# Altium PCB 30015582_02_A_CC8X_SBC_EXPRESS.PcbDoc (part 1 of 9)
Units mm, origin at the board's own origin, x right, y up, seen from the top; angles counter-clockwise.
Board outline 87 x 63 mm, 6 copper layers (Top Layer-L1, GND Plane-L2, Signal-L3, PWR/Signal-L4, GND Plane-L5, Bottom Layer-L6), stack 1.172 mm thick; 169 components, 171 nets, 693 pads, 391 vias.
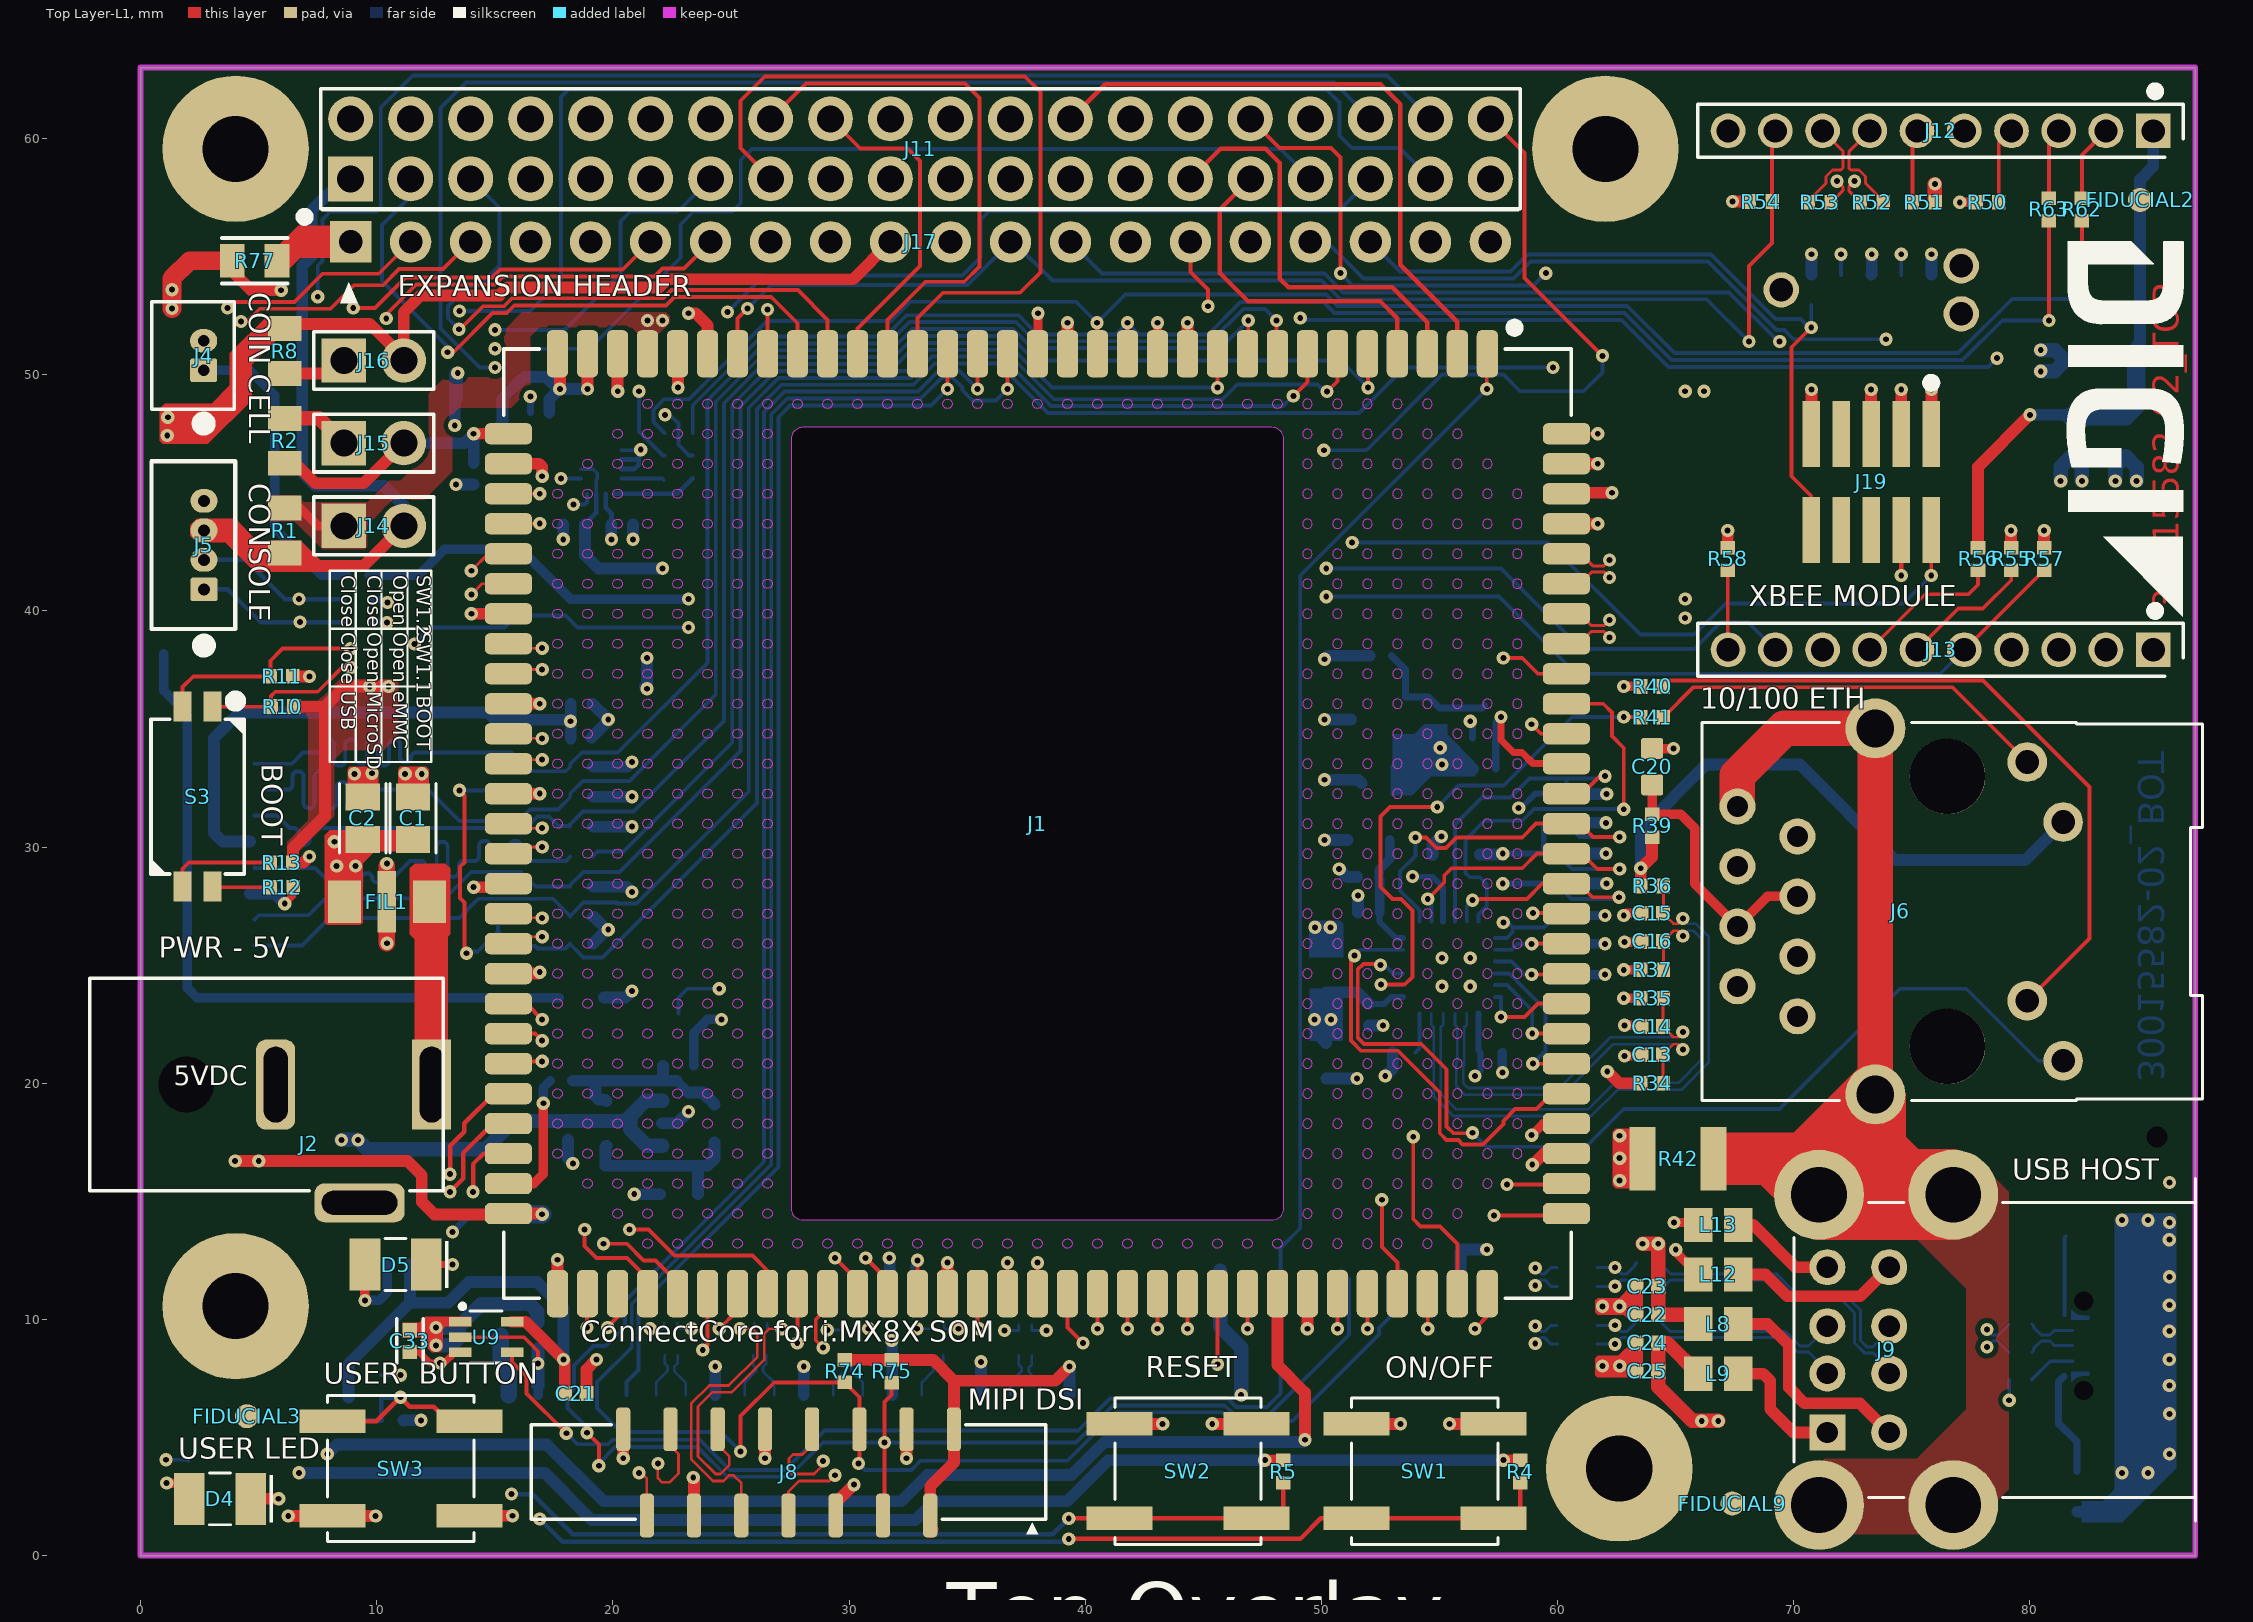
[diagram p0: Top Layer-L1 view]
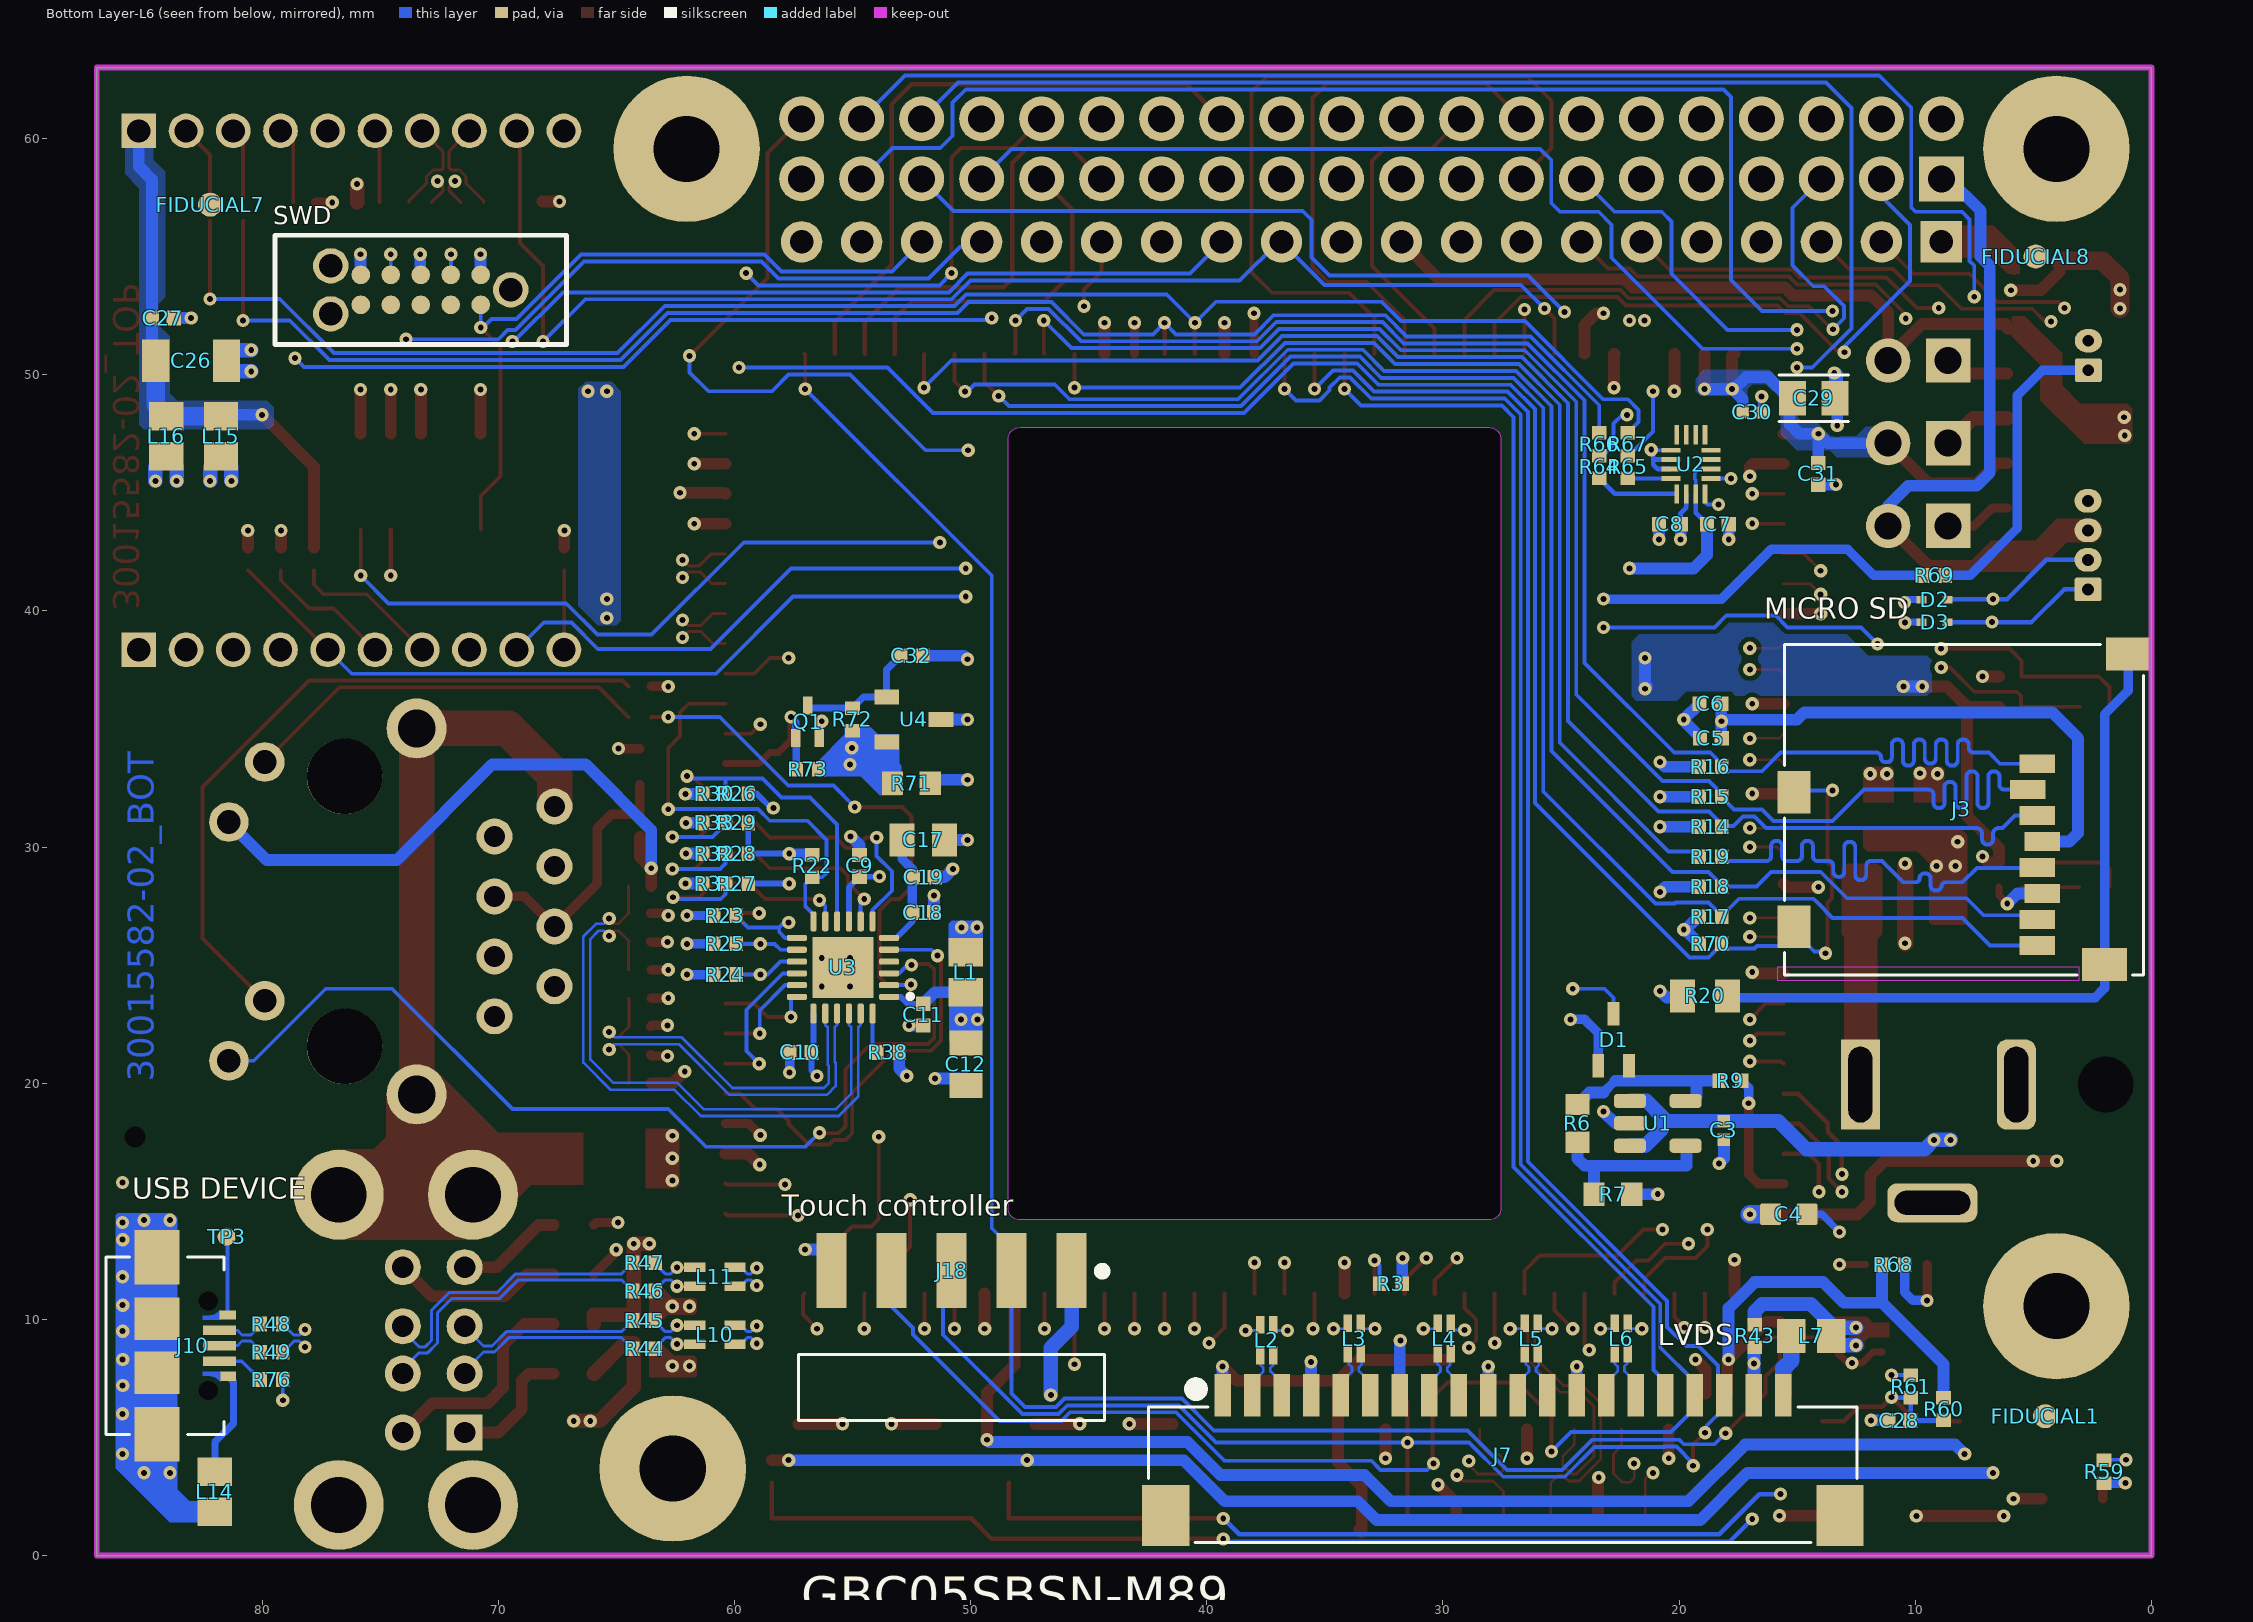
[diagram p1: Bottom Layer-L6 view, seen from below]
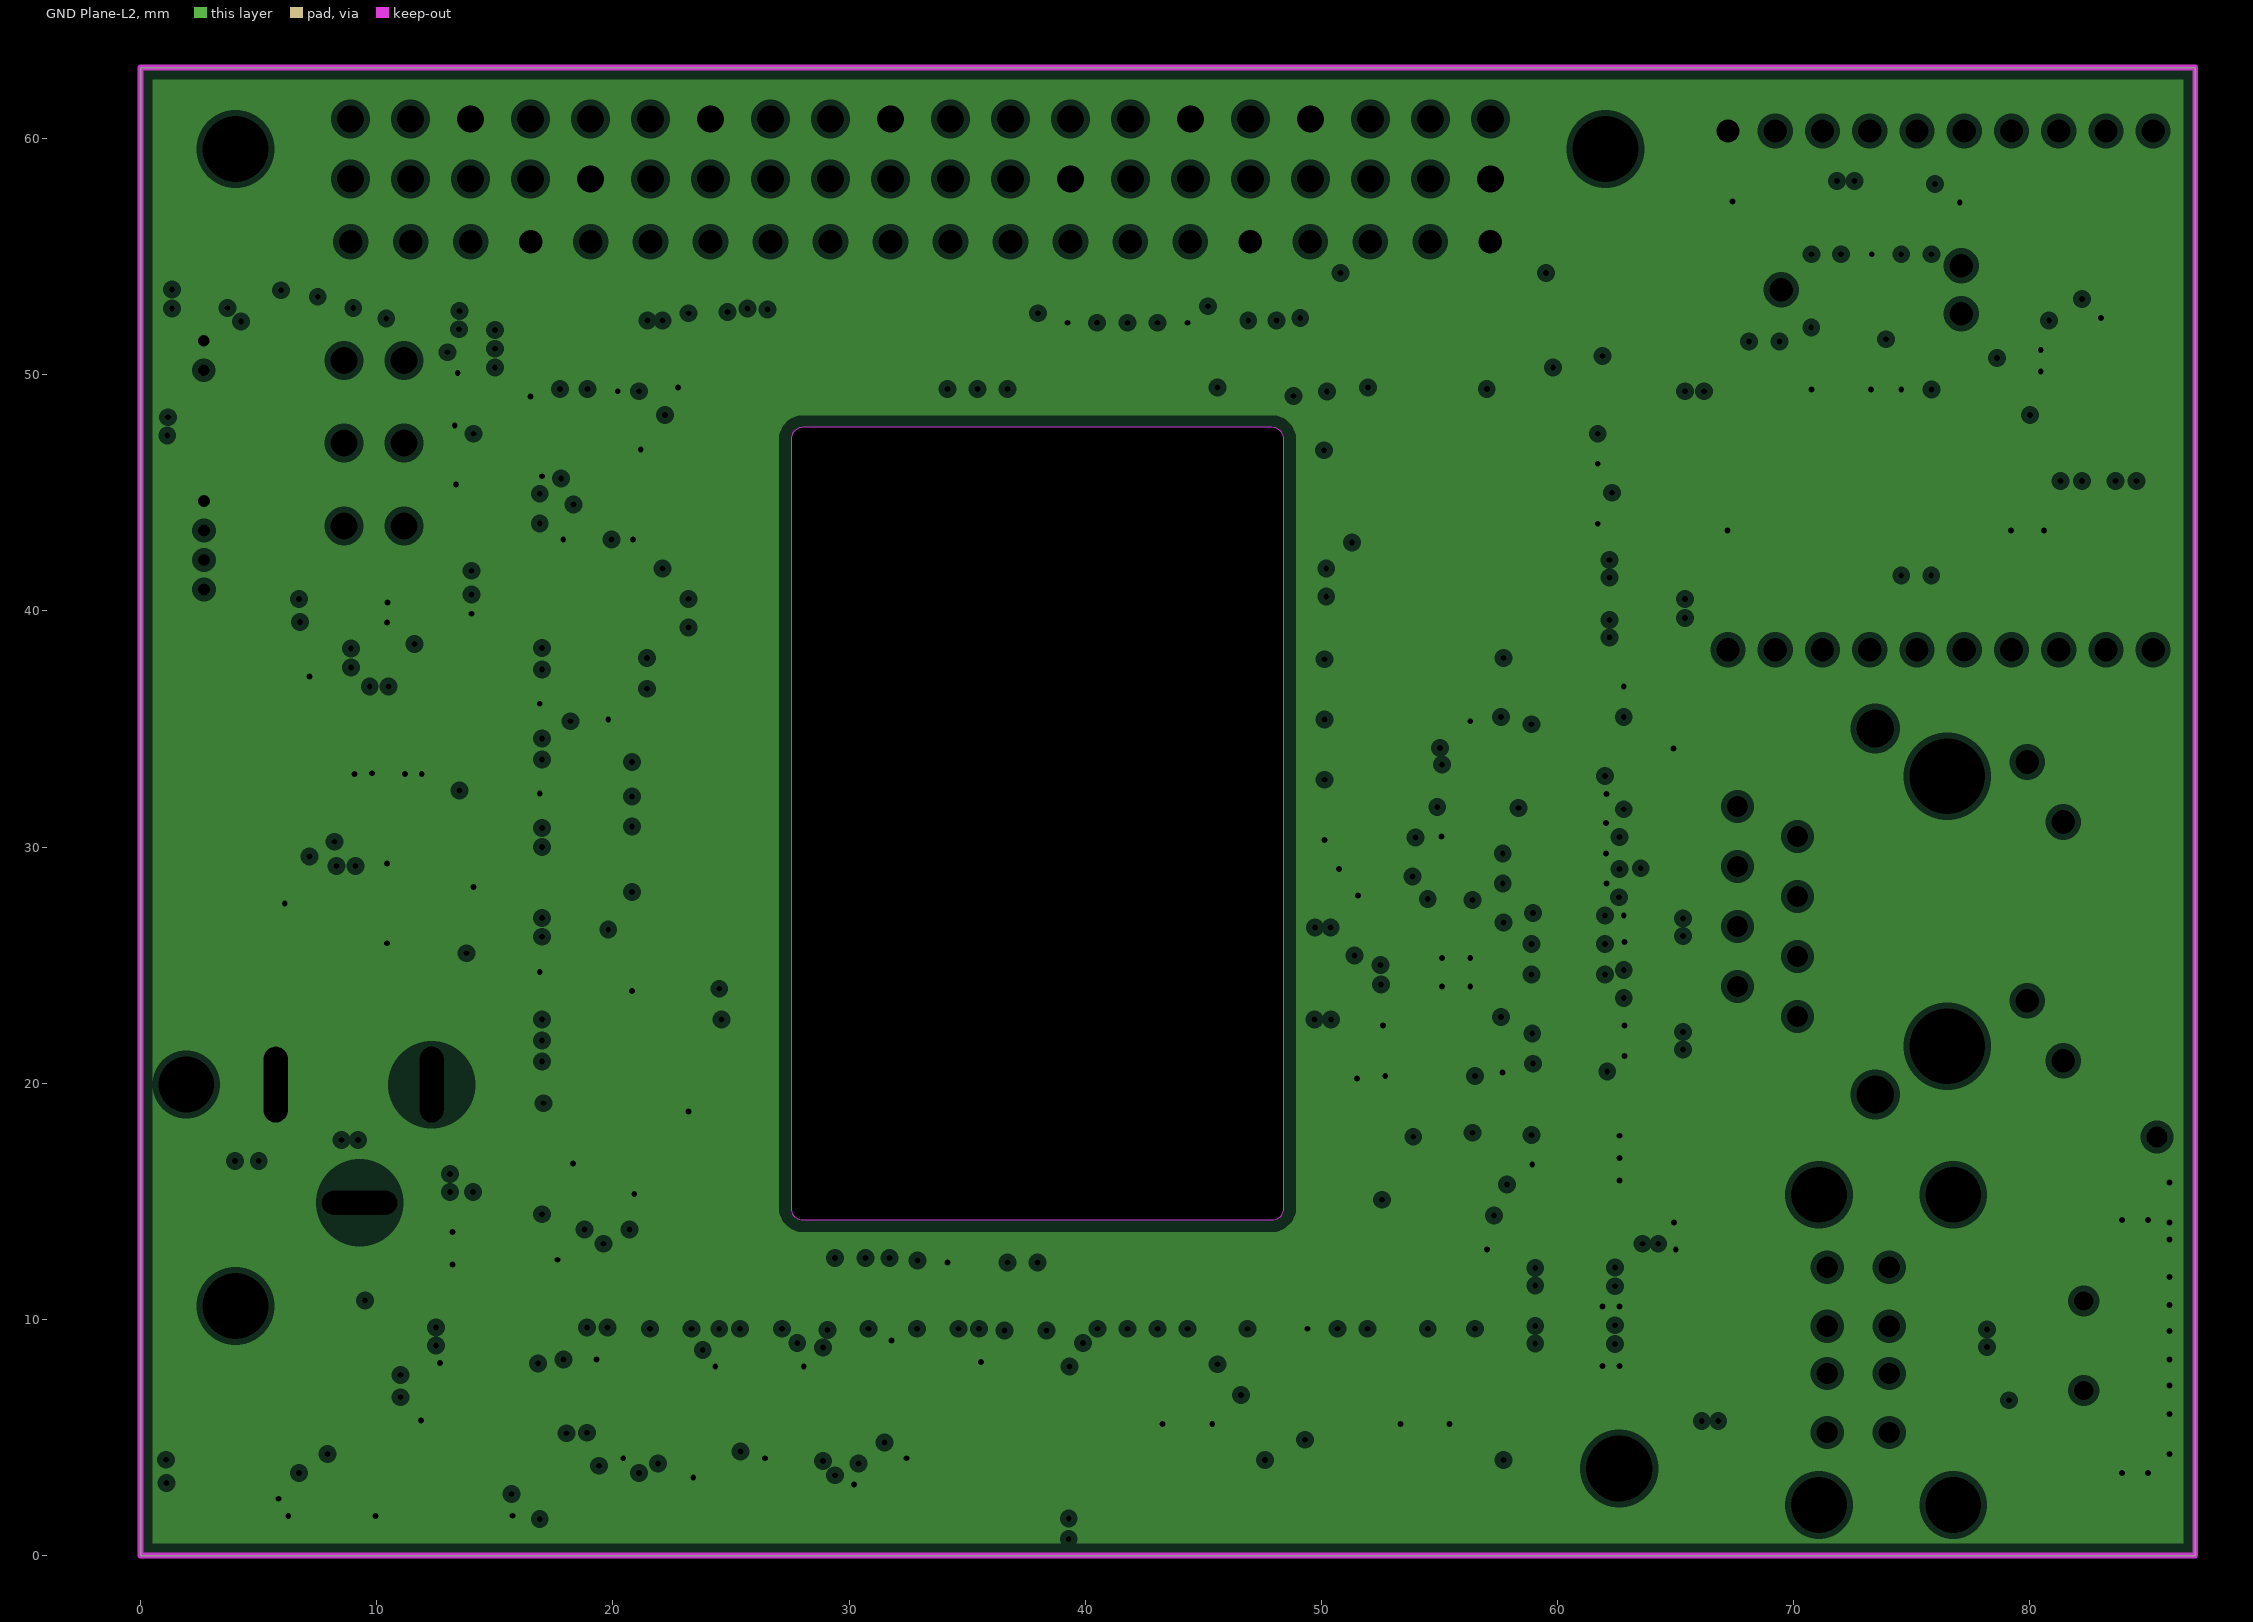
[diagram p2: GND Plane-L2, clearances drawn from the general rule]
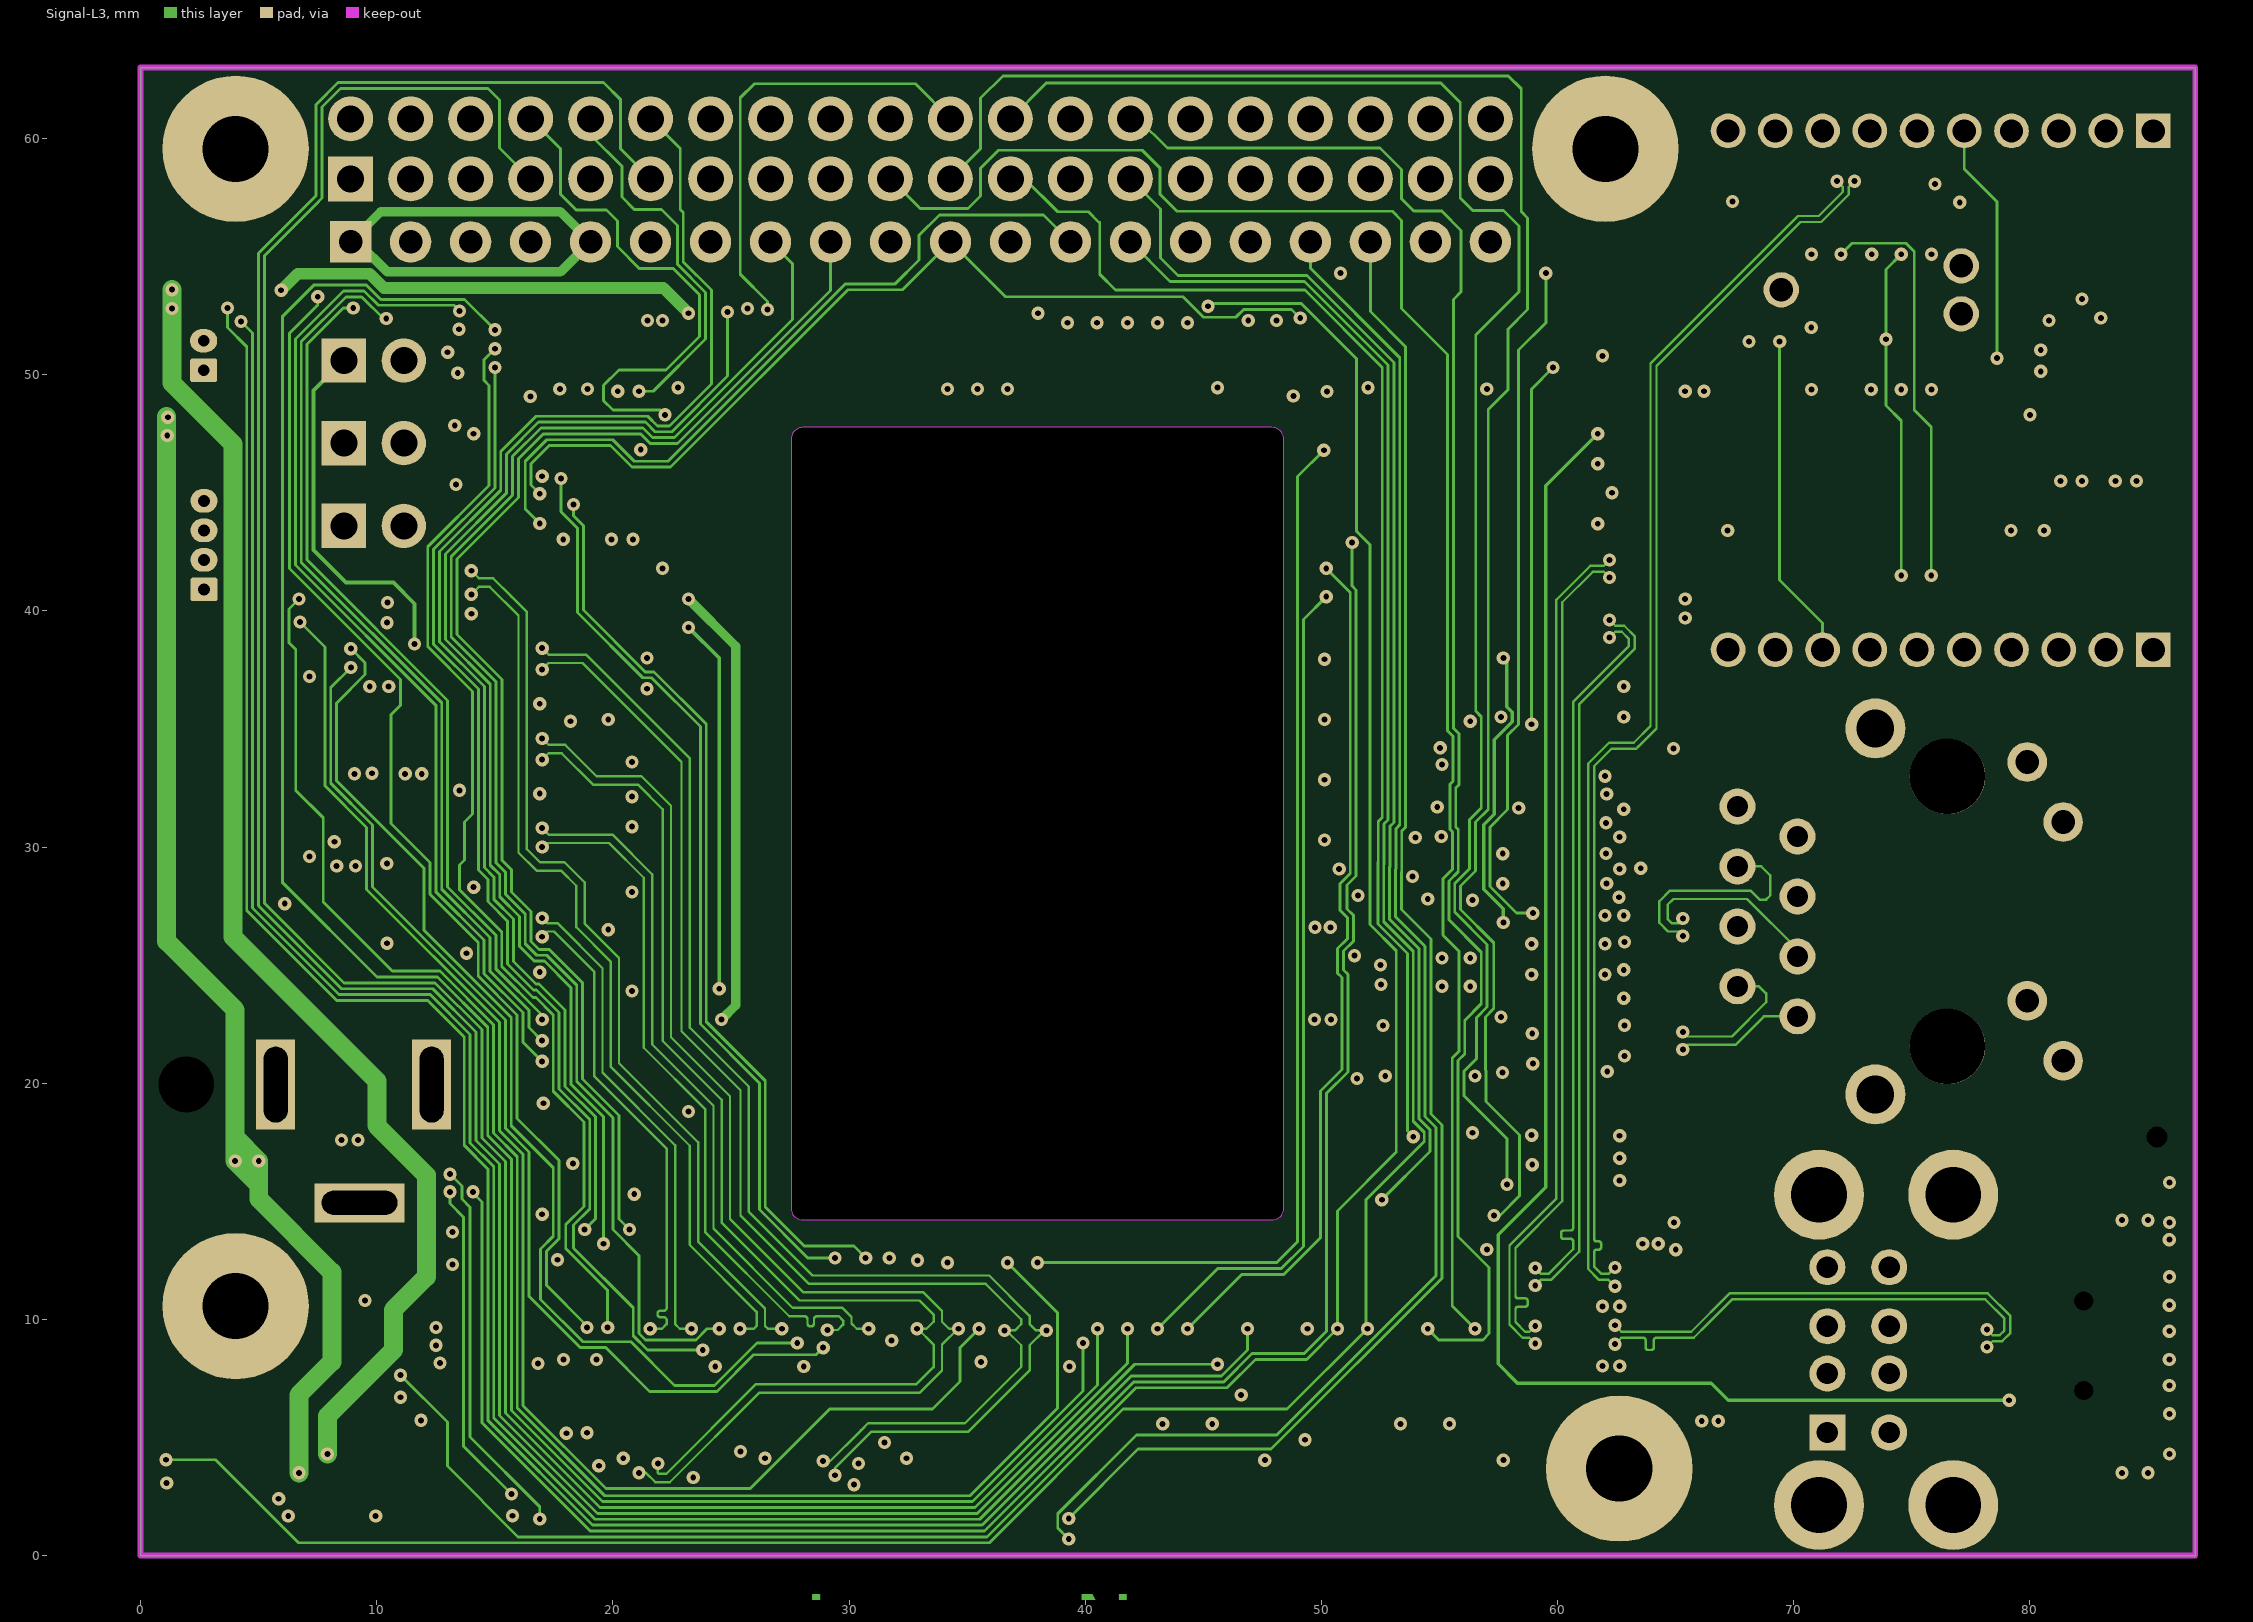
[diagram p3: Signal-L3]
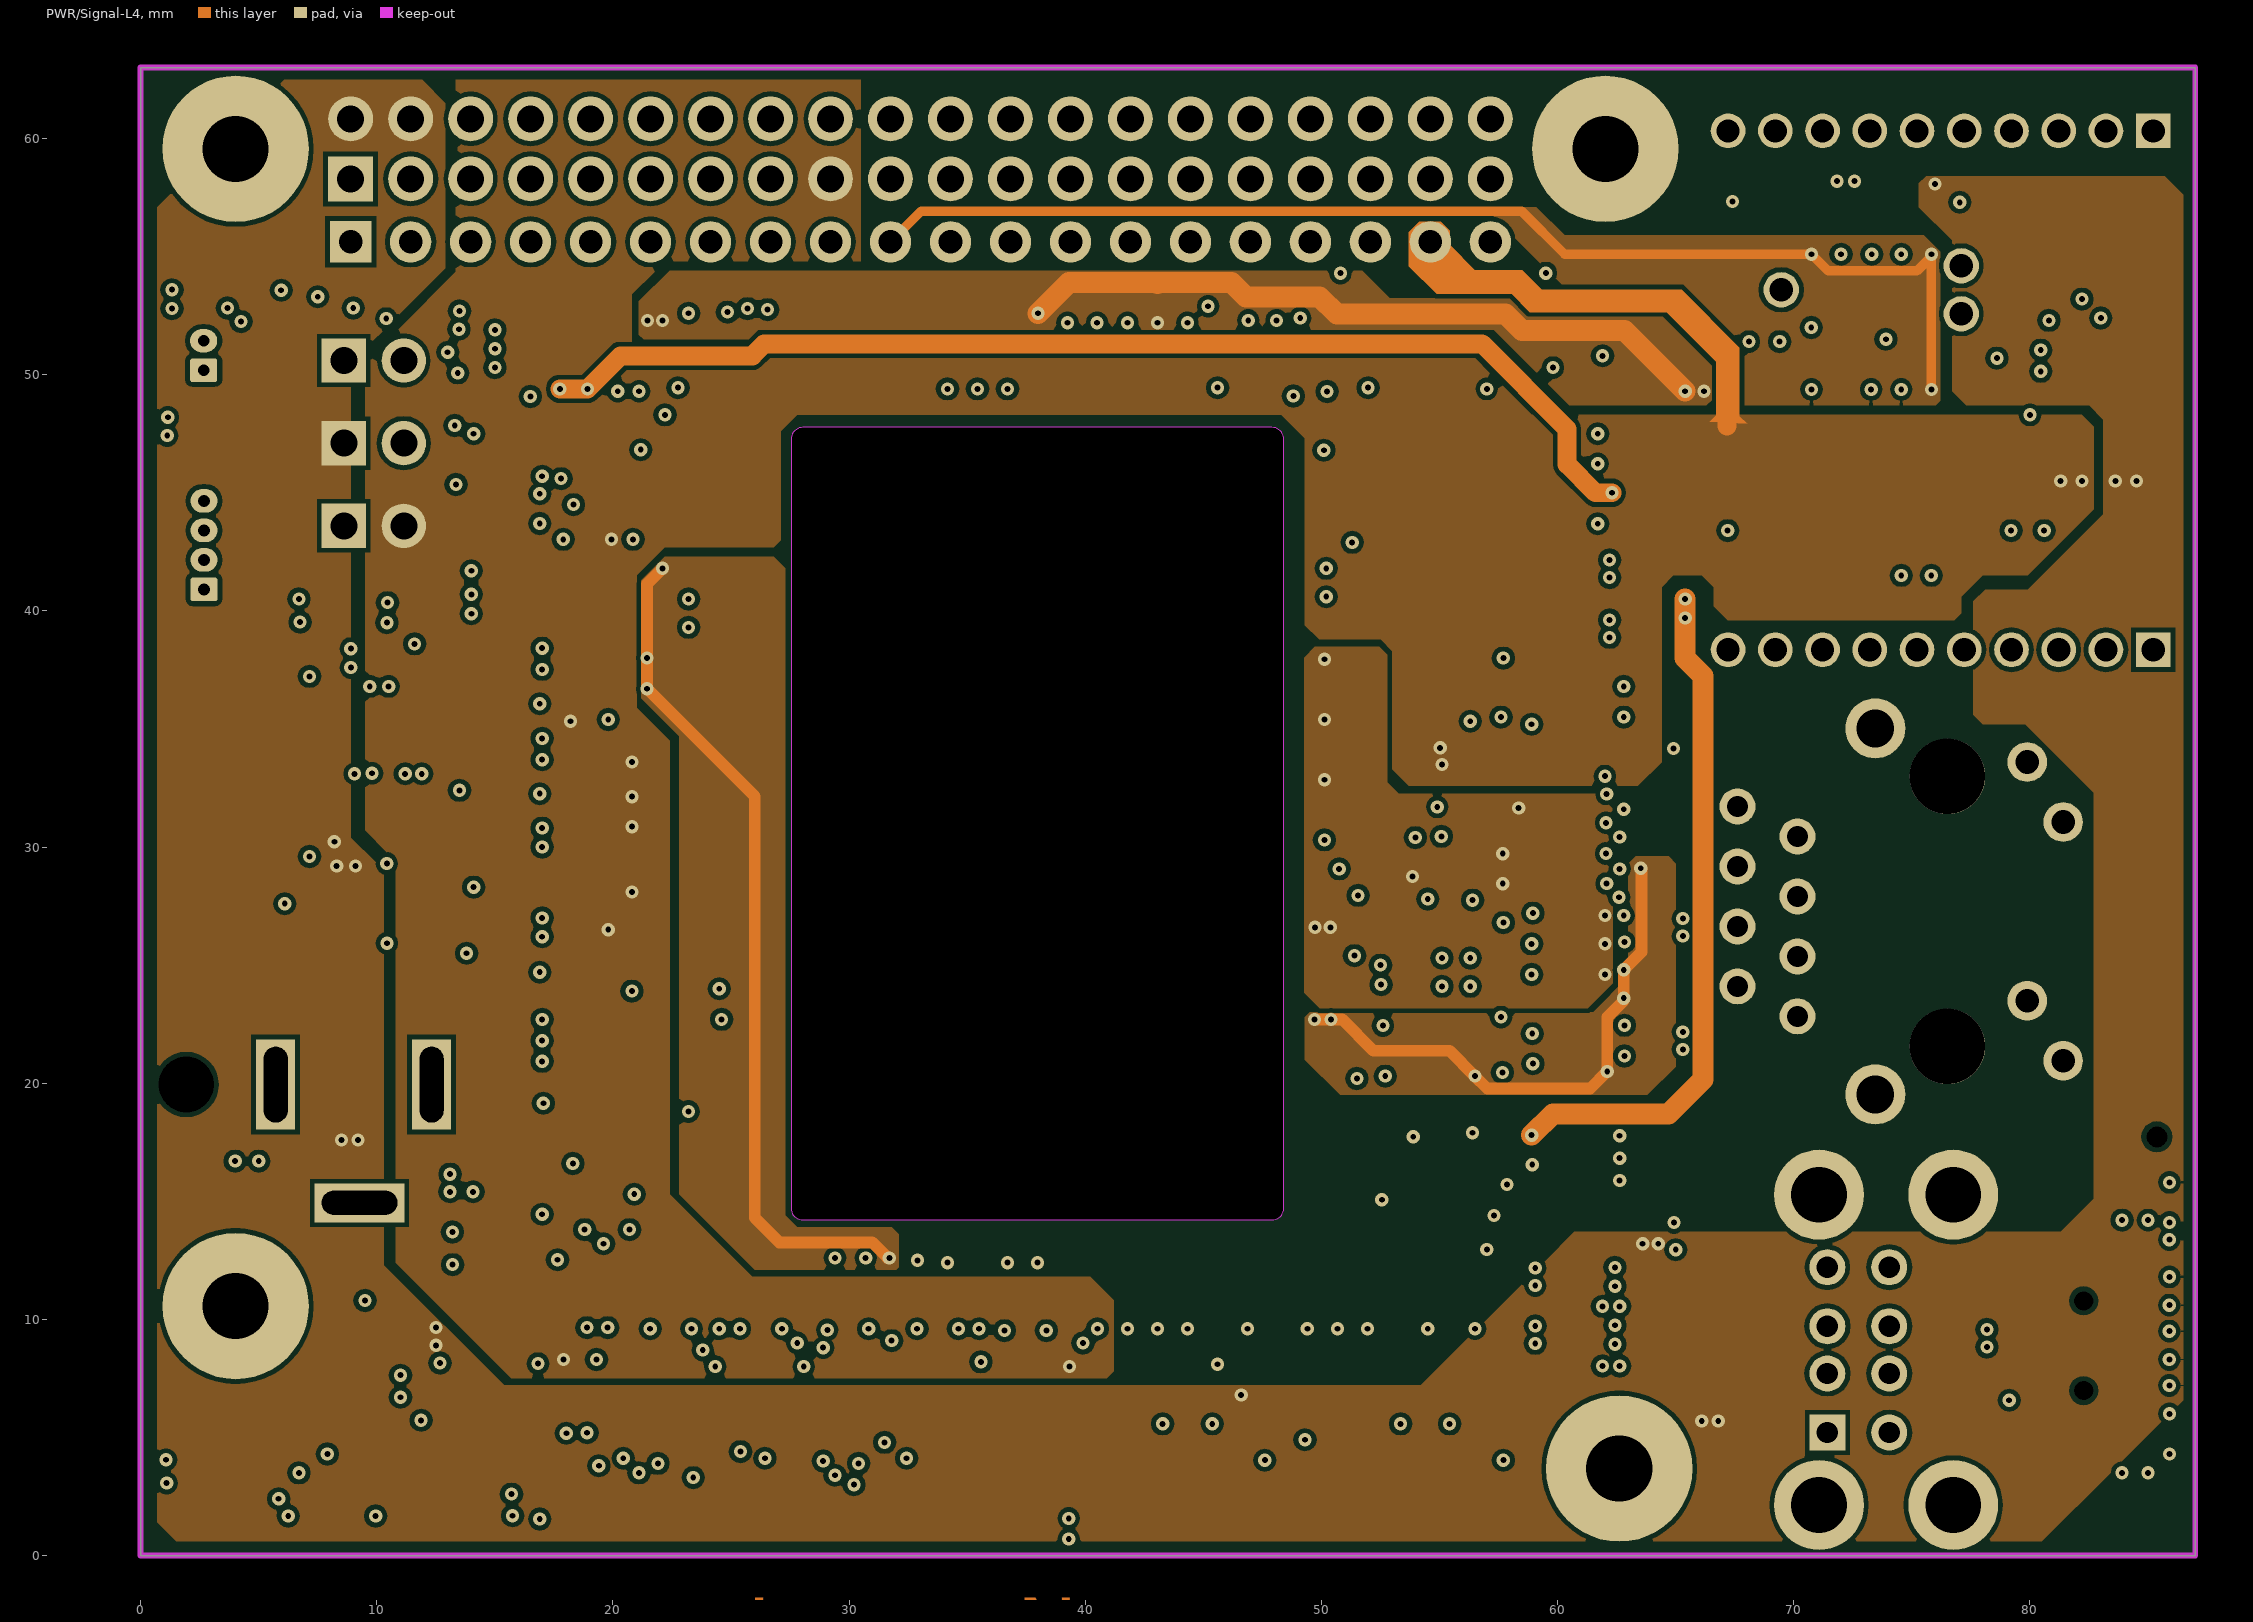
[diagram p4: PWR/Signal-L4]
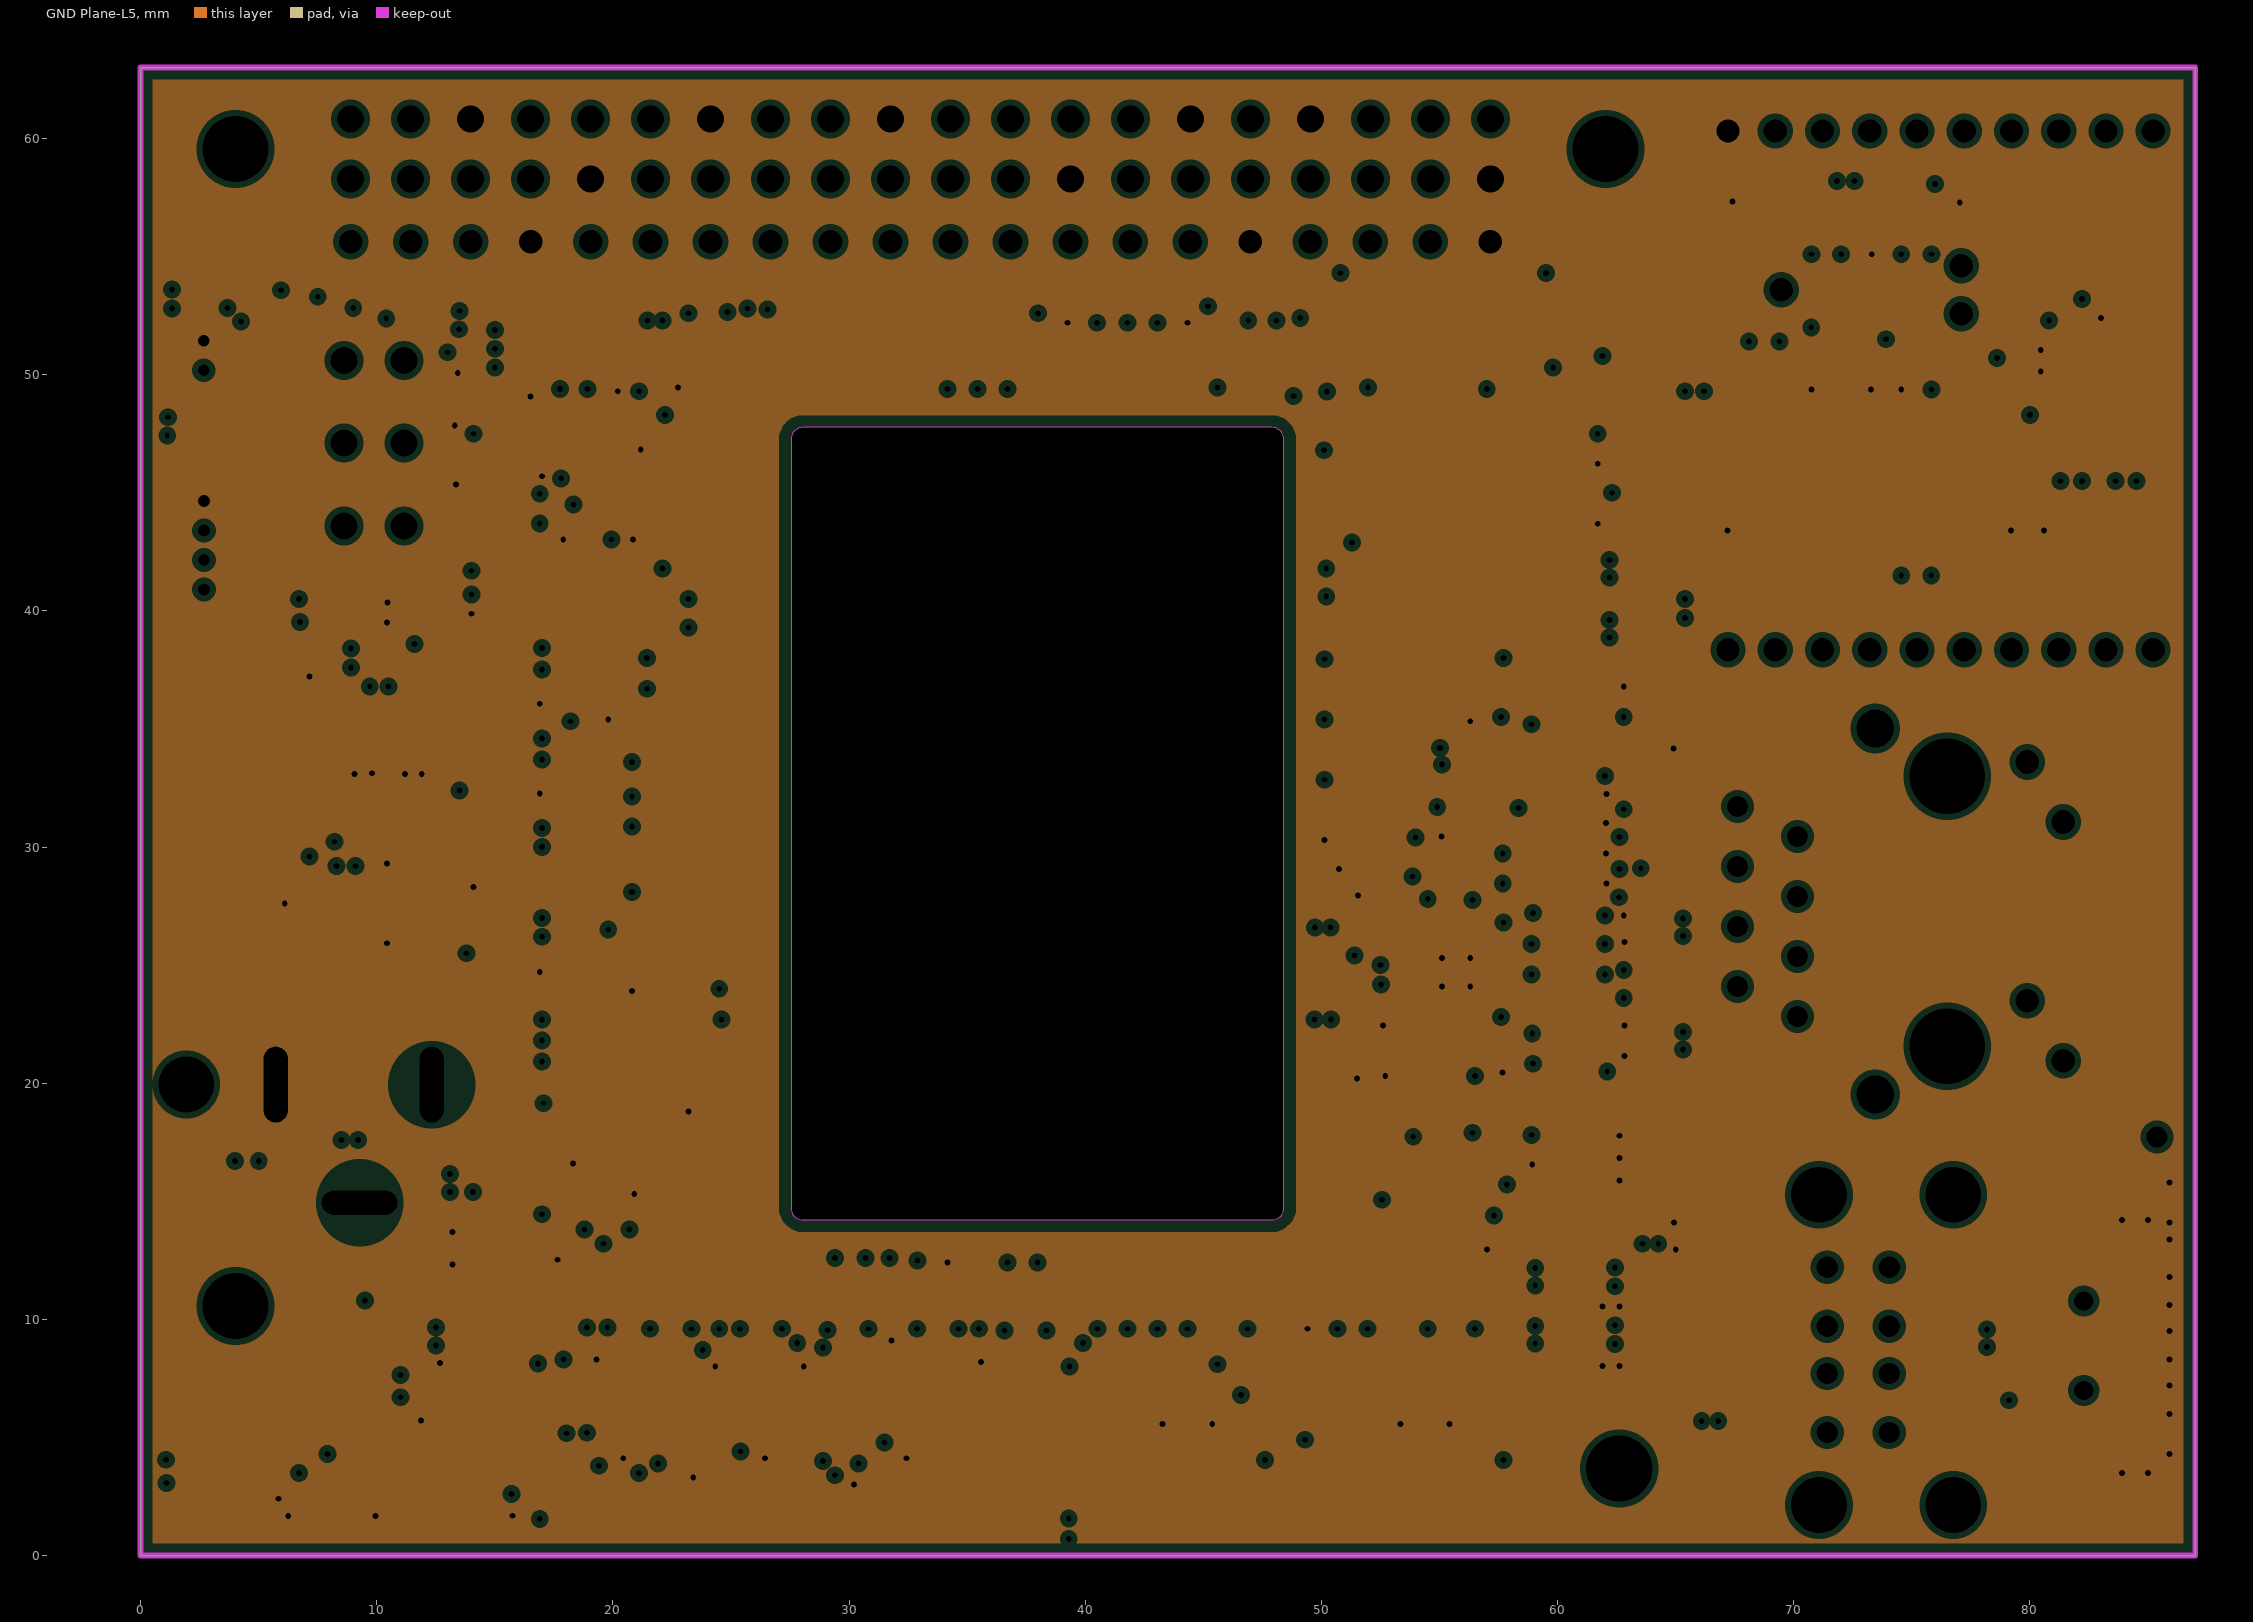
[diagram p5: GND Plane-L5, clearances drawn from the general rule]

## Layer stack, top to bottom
Top Solder: solder mask 0.0102, Solder Resist, Dk 3.5
Top Layer-L1: signal copper 0.048
Dielectric 1: prepreg 0.125, FR-4, Dk 4.2
GND Plane-L2: plane copper 0.0279, net GND
Dielectric 4: core 0.1016, FR-4, Dk 4
Signal-L3: signal copper 0.0279
Dielectric 5: prepreg 0.5116, FR-4, Dk 4.55
PWR/Signal-L4: signal copper 0.0279
Dielectric 2: core 0.1016, Dk 4
GND Plane-L5: plane copper 0.0279, net GND
Dielectric 3: prepreg 0.125, Dk 4.2
Bottom Layer-L6: signal copper 0.048
Bottom Solder: solder mask 0.0102, Solder Resist, Dk 3.5

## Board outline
0,0 0,63 87,63 87,0

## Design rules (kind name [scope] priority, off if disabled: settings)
Clearance "PAD TO PAD" [Ispad vs Ispad] p1 off: gap=0.3 ignorepadtopadclearanceinfootprint=FALSE except(0: Arc-Hole Track-Hole SMDPad-Hole THPad-Hole Via-Hole Fill-Hole Poly-Hole Region-Hole Text-Hole)
Clearance "via to pad" [IsPad vs (isvia)] p2 off: gap=0 ignorepadtopadclearanceinfootprint=FALSE
Clearance Clearance_PTH_to_SMT [IsPad AND InSMTComponent And OnBottom and not HasFootprint ('fiducial_40mil_round') vs IsThruPin AND InThruComponent  AND NOT InComponent ('MECH1') AND NOT InComponent ('P1') AND NOT InComponent ('J14')AND NOT InComponent ('J15') AND NOT InComponent ('J16') AND NOT InComponent('J2') AND NOT InComponent('SWD') AND NOT InComponent('JTAG')] p3: gap=5 ignorepadtopadclearanceinfootprint=FALSE except(0: Arc-Hole Track-Hole SMDPad-Hole THPad-Hole Via-Hole Fill-Hole Poly-Hole Region-Hole Text-Hole) // Clearance for PTH pins to SMT components
Clearance Clearance_Polygon_3V3 [InNamedPolygon('PWR/Singal-L4-3V3') vs IsTrack OR InPoly] p4: gap=0.5 ignorepadtopadclearanceinfootprint=FALSE except(0: Arc-Hole Track-Hole SMDPad-Hole THPad-Hole Via-Hole Fill-Hole Poly-Hole Region-Hole Text-Hole)
Clearance Clearance_50ohm_RF [InNetClass('50ohm_RF') vs InPoly OR IsVia] p5: gap=0.2 ignorepadtopadclearanceinfootprint=FALSE except(0: Arc-Hole Track-Hole SMDPad-Hole THPad-Hole Via-Hole Fill-Hole Poly-Hole Region-Hole Text-Hole) // Dielectric thickness = 10mil; Width = 17.9mil; Top and Bot, Ref layer 3 and 4
Clearance Clearance_Board_Edge [OnLayer('Keep-Out Layer') vs InPoly] p6: gap=0.381 ignorepadtopadclearanceinfootprint=FALSE except(0: Arc-Hole Track-Hole SMDPad-Hole THPad-Hole Via-Hole Fill-Hole Poly-Hole Region-Hole Text-Hole)
Clearance Clearance_CONNECTORS [HasFootprint ('HIROSE_A2-20PA-2.54DSA(71)') OR HasFootprint ('Wurth_61304021121')] p7: gap=0.2 ignorepadtopadclearanceinfootprint=FALSE except(0: Arc-Hole Track-Hole SMDPad-Hole THPad-Hole Via-Hole Fill-Hole Poly-Hole Region-Hole Text-Hole)
Clearance Clearance_Polygon [InPoly] p8: gap=0.2 ignorepadtopadclearanceinfootprint=FALSE except(0: Arc-Hole Track-Hole SMDPad-Hole THPad-Hole Via-Hole Fill-Hole Poly-Hole Region-Hole Text-Hole)
Clearance Clearance_General [All] p9: gap=0.127 ignorepadtopadclearanceinfootprint=FALSE except(0: Arc-Hole Track-Hole SMDPad-Hole THPad-Hole Via-Hole Fill-Hole Poly-Hole Region-Hole Text-Hole; 0.177: SMDPad-Via THPad-Via Via-Via; 0.2: Arc-SMDPad Arc-THPad Track-SMDPad Track-THPad)
ComponentClearance [All] p1 off: gap=0.254 collisioncheckmode=3 verticalgap=0.254 showdistances=FALSE
ComponentClearance "Clearance Generic" [All] p2 off: gap=0.102 collisioncheckmode=3 verticalgap=-1.27 showdistances=FALSE
DiffPairsRouting DiffPairsRouting_100ohm [InDifferentialPairClass('100OHM')] p1: maxlimit=0.254 minlimit=0.178 mostfreqgap=0.254 toplayer_maxgap=0.178 toplayer_prefgap=0.178 toplayer_minwidth=0.114 toplayer_maxwidth=0.114 toplayer_prefwidth=0.114 midlayer2_mingap=0.254 midlayer2_minwidth=0.102 midlayer2_maxwidth=0.102 midlayer2_prefwidth=0.102 midlayer3_mingap=0.254 midlayer3_minwidth=0.102 midlayer3_maxwidth=0.102 midlayer3_prefwidth=0.102 bottomlayer_maxgap=0.178 bottomlayer_prefgap=0.178 bottomlayer_minwidth=0.114 bottomlayer_maxwidth=0.114 bottomlayer_prefwidth=0.114 maxuncoupledlength=12.7
DiffPairsRouting DiffPairsRouting_90ohm [InDifferentialPairClass('90OHM')] p2: maxlimit=0.152 minlimit=0.127 mostfreqgap=0.152 toplayer_maxgap=0.127 toplayer_prefgap=0.127 toplayer_minwidth=0.127 toplayer_maxwidth=0.127 toplayer_prefwidth=0.127 midlayer2_mingap=0.152 midlayer2_minwidth=0.102 midlayer2_maxwidth=0.102 midlayer2_prefwidth=0.102 midlayer3_mingap=0.152 midlayer3_minwidth=0.102 midlayer3_maxwidth=0.102 midlayer3_prefwidth=0.102 bottomlayer_maxgap=0.127 bottomlayer_prefgap=0.127 bottomlayer_minwidth=0.127 bottomlayer_maxwidth=0.127 bottomlayer_prefwidth=0.127 maxuncoupledlength=12.7
FabricationTestPointUsage TestPointUsage [All] p1: valid=0 allowmultiple=FALSE
FabricationTestpoint Testpoint [All] p1: side=3 testpointundercomponent=TRUE minsize=1.016 maxsize=2.54 preferedsize=1.524 minholesize=0 maxholesize=1.016 preferedholesize=0.813 testpointgrid=0.025 allowsidetop=TRUE allowsidebottom=TRUE usegrid=TRUE gridtolerance=0
HoleSize [All] p1: absolutevalues=TRUE maxlimit=3.35 minlimit=0.25 maxpercent=80.000 minpercent=20.000
MinimumAnnularRing [All] p1: minimumring=0.127
MinimumSolderMaskSliver [All vs All and not inComponent('SWD') and not InComponent('JTAG')] p1: minsoldermaskwidth=0.075
PlaneClearance [All] p1: clearance=0.254
PlaneConnect "Via_ Direct_Connect_to_Plane" [IsVia] p1: planeconnectstyle=Direct reliefexpansion=0.508 reliefentries=4 reliefconductorwidth=0.254 reliefairgap=0.254
PlaneConnect [All] p2: planeconnectstyle=Direct reliefexpansion=0.508 reliefentries=4 reliefconductorwidth=0.254 reliefairgap=0.254
PolygonConnect PolygonConnect_Via [IsVia] p1: connectstyle=Direct reliefconductorwidth=0.254 reliefentries=4 polygonreliefangle="90 Angle" airgapwidth=0.254
PolygonConnect PolygonConnect_POLYSOLID [IsNamedPolygon('Polysolid')] p2: connectstyle=Direct reliefconductorwidth=0.254 reliefentries=4 polygonreliefangle="90 Angle" airgapwidth=0.254
PolygonConnect [All] p3: connectstyle=Relief reliefconductorwidth=0.254 reliefentries=4 polygonreliefangle="90 Angle" airgapwidth=0.254
RoutingVias [All] p1: holewidth=0.25 width=0.56 viastyle="Through Hole" minholewidth=0.25 minwidth=0.56 maxholewidth=0.25 maxwidth=0.56
ShortCircuit [InComponent('P1') vs OnLayer('Top Layer-L1')] p1: allowed=TRUE
SilkToSilkClearance [All] p1: silktosilkclearance=0.102
SilkToSolderMaskClearance SilkscreenOverComponentPads [IsPad] p1 off: minsilkscreentomaskgap=0.025 clearancetoexposedcopper=TRUE
SolderMaskExpansion SolderMaskExpansion_VIA [ISVIA] p1: expansion=0
SolderMaskExpansion [All] p2: expansion=0.051
Width Width_50ohm_RF [InNetClass('50ohm_RF')] p1: maxlimit=0.455 minlimit=0.455 preferedwidth=0.455 midlayer2_minwidth=0 midlayer2_maxwidth=0 midlayer2_prefwidth=0 midlayer3_minwidth=0 midlayer3_maxwidth=0 midlayer3_prefwidth=0 minimp=50.000000 maximp=50.000000 favimp=50.000000 // Dielectric thickness = 10mil; Gap = 8; Top and Bot, Ref layer 3 and 4
Width Width_50ohm_SE [InNetClass('50ohm_SE')] p2: maxlimit=0.191 minlimit=0.121 preferedwidth=0.191 toplayer_minwidth=0.165 midlayer2_maxwidth=0.122 midlayer2_prefwidth=0.122 midlayer3_maxwidth=0.122 midlayer3_prefwidth=0.122 bottomlayer_minwidth=0.165 minimp=50.000000 maximp=50.000000 favimp=50.000000
Width "Width 2 Amps" [InNetClass('2A')] p3: maxlimit=1.651 minlimit=0.61 preferedwidth=1.524 toplayer_maxwidth=0.762 toplayer_prefwidth=0.61 midlayer2_minwidth=1.397 midlayer3_minwidth=1.397 bottomlayer_maxwidth=0.762 bottomlayer_prefwidth=0.61 minimp=50.000000 maximp=50.000000 favimp=50.000000
Width "Width 1.25Amps" [InNetClass('1.25A')] p4: maxlimit=1.016 minlimit=0.33 preferedwidth=0.889 toplayer_maxwidth=0.381 toplayer_prefwidth=0.33 midlayer2_minwidth=0.889 midlayer3_minwidth=0.889 bottomlayer_maxwidth=0.381 bottomlayer_prefwidth=0.33 minimp=50.000000 maximp=50.000000 favimp=50.000000
Width [All] p5: maxlimit=3 minlimit=0.15 preferedwidth=0.15 minimp=50.000000 maximp=50.000000 favimp=50.000000
19 further rules are at their usual default settings.

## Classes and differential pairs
net class POWERS: 1V8 3V3 3V3_ETH0 3V3_EXT 5V_CC8X AVDD1 VCC_LICELL VCC_MCA VCC_SCU_1V8 VDDCR1 VIN XBEE_VCC
net class 50ohm_SE: ADC_IN0 ADC_IN1 CONSOLE_RX CONSOLE_TX ENET0_RX_CTL ENET0_RX_ER ENET0_RXD0 ENET0_RXD1 ETH0_LED1/#REGOFF ETH0_LED2/#NINTSEL EXPANSION_UART_RX EXPANSION_UART_TX GPIO1_17 GPIO1_18 GPIO1_19 GPIO1_20 GPIO1_28 GPIO1_29 GPIO1_30 GPIO3_15 GPIO4_20 GPIO4_21 GPIO4_22 GPIO5_03 I2C2_SCL I2C2_SDA I2C3_SCL I2C3_SDA MCA_IO1 MCA_IO2 MCA_IO3 MCA_IO4 MCA_IO5 MCA_IO6 MCA_IO7 MCA_IO8 MCA_IO9 MCA_IO10 MIPI_DSI0_I2C0_SCL MIPI_DSI0_I2C0_SDA MIPI_DSI0_IRQ_N MIPI_DSI0_PWM0_OUT NetJ1_72 NetJ3_5 NetJ12_2 NetJ12_3 NetJ12_4 NetJ12_6 SCU_BOOT_MODE0 SCU_BOOT_MODE1 SD_CARD_DETECT SPI3_CS0 SPI3_SCK SPI3_SDI SPI3_SDO SWD_CLK/PWR_IO SWD_DIO/MCA_IO21 SYS_RESET UART3_RX UART3_TX USDHC1_CLK USDHC1_CMD USDHC1_DATA0 USDHC1_DATA1 USDHC1_DATA2 USDHC1_DATA3 USER_BUTTON USER_LED XBEE_ON/SLP_N XBEE_RESET XBEE_SLEEP_RQ XBEE_UART_CTS XBEE_UART_RTS XBEE_UART_RX XBEE_UART_TX
net class 2A: VIN
net class 1.25A: 3V3
differential pair class 90OHM: USB USB_OTG1 USB_OTG1_FIL USB_OTG1_FIL_ USB_OTG1_FIL_X USB_OTG2 USB_OTG2_FIL USB_OTG2_FIL_ USB_OTG2_FIL_A USB_OTG2_FIL_X
differential pair class 100OHM: D_ETH0_RX D_ETH0_TX D_MIPI_DSI0_CLK D_MIPI_DSI0_DATA0 D_MIPI_DSI0_DATA1 D_MIPI_DSI0_DATA2 D_MIPI_DSI0_DATA3 ETH0_RX ETH0_TX MIPI_DSI0_CLK_ MIPI_DSI0_DATA0_ MIPI_DSI0_DATA1_ MIPI_DSI0_DATA2_ MIPI_DSI0_DATA3_
component class "03 - Power, boot mode, reset, console, microSD, SWD, Coin Cell": C1 C2 C3 C4 C5 C6 D1 D2 D3 D5 FIL1 J2 J3 J4 J5 J16 J19 R4 R5 R6 R7 R8 R9 R10 R11 R12 R13 R14 R15 R16 R17 R18 R19 R20 R68 R69 R70 S3 SW1 SW2 SWD U1
component class "04 - 10-100 Mb Ethernet, LVDS, MIPI": C9 C10 C11 C12 C13 C14 C15 C16 C17 C18 C19 C20 C21 C32 C33 J6 J7 J8 J18 L1 L2 L3 L4 L5 L6 L7 Q1 R22 R23 R24 R25 R26 R27 R28 R29 R30 R31 R32 R33 R34 R35 R36 R37 R38 R39 R40 R41 R42 R43 R71 R72 R73 R74 R75 U3 U4 U9
component class "05 - USB Host-Device, Raspberry PI expansion, User LED and button, XBee": C7 C8 C22 C23 C24 C25 C26 C27 C28 D4 J9 J10 J11 J12 J13 J17 L8 L9 L10 L11 L12 L13 L14 L15 L16 R44 R45 R46 R47 R48 R49 R50 R51 R52 R53 R54 R55 R56 R57 R58 R59 R60 R61 R62 R63 R64 R65 R66 R67 R76 SW3 TP3 U2
component class "07 - History, Mechanicals": FIDUCIAL1 FIDUCIAL2 FIDUCIAL3 FIDUCIAL7 FIDUCIAL8 FIDUCIAL9 PCB1
net class DIFF90: USB_OTG1_FIL_N USB_OTG1_FIL_P USB_OTG1_N USB_OTG1_P USB_OTG2_FIL_N USB_OTG2_FIL_P USB_OTG2_N USB_OTG2_P
net class DIFF100: ETH0_RX_N ETH0_RX_P ETH0_TX_N ETH0_TX_P
net class MICROSD: NetJ3_5 NetJ3_11 SD_CARD_DETECT USDHC1_CLK USDHC1_CMD USDHC1_DATA0 USDHC1_DATA1 USDHC1_DATA2 USDHC1_DATA3
component class "02 - CC8X Module": C29 C30 C31 J1 J14 J15 R1 R2 R3 R77
differential pair USB_OTG2_FIL_: +NetJ9_B3 -NetJ9_B2
differential pair USB_OTG1_FIL_X: +NetJ10_3 -NetJ10_2
differential pair USB_OTG1_FIL_: +NetJ9_A3 -NetJ9_A2
differential pair MIPI_DSI0_DATA3_: +NetJ7_15 -NetJ7_14
differential pair MIPI_DSI0_DATA2_: +NetJ7_9 -NetJ7_8
differential pair MIPI_DSI0_DATA1_: +NetJ7_6 -NetJ7_5
differential pair MIPI_DSI0_DATA0_: +NetJ7_3 -NetJ7_2
differential pair MIPI_DSI0_CLK_: +NetJ7_12 -NetJ7_11
differential pair D_USB_OTG2: +USB_OTG2_P -USB_OTG2_N
differential pair D_USB_OTG2_FIL: +USB_OTG2_FIL_P -USB_OTG2_FIL_N
differential pair D_USB_OTG1: +USB_OTG1_P -USB_OTG1_N
differential pair D_USB_OTG1_FIL: +USB_OTG1_FIL_P -USB_OTG1_FIL_N
differential pair D_MIPI_DSI0_DATA3: +MIPI_DSI0_DATA3_P -MIPI_DSI0_DATA3_N
differential pair D_MIPI_DSI0_DATA2: +MIPI_DSI0_DATA2_P -MIPI_DSI0_DATA2_N
differential pair D_MIPI_DSI0_DATA1: +MIPI_DSI0_DATA1_P -MIPI_DSI0_DATA1_N
differential pair D_MIPI_DSI0_DATA0: +MIPI_DSI0_DATA0_P -MIPI_DSI0_DATA0_N
differential pair D_MIPI_DSI0_CLK: +MIPI_DSI0_CLK_P -MIPI_DSI0_CLK_N
differential pair D_ETH0_TX: +ETH0_TX_P -ETH0_TX_N
differential pair D_ETH0_RX: +ETH0_RX_P -ETH0_RX_N
differential pair USB_OTG2_FIL_A: +NetJ12_7 -NetJ12_8
differential pair USB_OTG2: +USB_OTG2_P -USB_OTG2_N
differential pair USB_OTG2_FIL: +USB_OTG2_FIL_P -USB_OTG2_FIL_N
differential pair USB_OTG1: +USB_OTG1_P -USB_OTG1_N
differential pair USB_OTG1_FIL: +USB_OTG1_FIL_P -USB_OTG1_FIL_N
differential pair ETH0_RX: +ETH0_RX_P -ETH0_RX_N
differential pair ETH0_TX: +ETH0_TX_P -ETH0_TX_N

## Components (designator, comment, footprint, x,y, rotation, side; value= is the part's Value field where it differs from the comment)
C1 "47uF" CAPC2013X145N 11.535,31.221 r270 top
C2 "47uF" CAPC2013X145N 9.4,31.225 r270 top
C3 "1.0uF" CAPC1005X55L 18.1,18 r90 bottom
C4 "2.2UF" CAPC1608X90N 15.35,14.45 r0 bottom
C5 "10uF" CAPC1005X55N 18.65,34.6 r180 bottom
C6 "100nF" CAPC1005X55N 18.669,36.068 r180 bottom
C7 "100nF" CAPC1005X55N 18.353,43.665 r0 bottom
C8 "100nF" CAPC1005X55N 20.385,43.665 r180 bottom
C9 "100nF" CAPC1005X55N 54.7,29.2 r90 bottom
C10 "100nF" CAPC1005X55N 57.2,21.3 r180 bottom
C11 "100nF" CAPC1005X55N 52,22.9 r270 bottom
C12 "4.7uF" CAPC2013X135N 50.2,20.8 r90 bottom
C13 "100nF" CAPC1005X55N 64,21.2 r180 top
C14 "100nF" CAPC1005X55N 64,22.4 r180 top
C15 "100nF" CAPC1005X55N 64,27.2 r180 top
C16 "100nF" CAPC1005X55N 64,26 r180 top
C17 "4.7uF" CAPC2013X135N 52,30.3 r0 bottom
C18 "1.0uF" CAPC1005X55N 52,27.225 r0 bottom
C19 "470pF" CAPC1005X55N 51.975,28.725 r0 bottom
C20 "22nF" CAPC1608X90N 64,33.4 r270 top
C21 "100nF" CAPC1005X55N 18.415,6.858 r180 top
C22 "10uF" CAPC1005X55N 63.8,10.2 r0 top
C23 "100nF" CAPC1005X55N 63.8,11.4 r0 top
C24 "10uF" CAPC1005X55N 63.8,9 r0 top
C25 "100nF" CAPC1005X55N 63.8,7.8 r0 top
C26 "100uF" CAPC3216X190N 83,50.6 r180 bottom
C27 "100nF" CAPC1005X55N 84.2,52.4 r0 bottom
C28 "100nF" CAPC1005X55N 10.668,5.715 r180 bottom
C29 "47uF" CAPC2013X145N 14.3,49 r0 bottom
C30 "1.0uF" CAPC1005X55L 16.9,48.4 r0 bottom
C31 "100nF" CAPC1005X55N 14.1,45.8 r270 bottom
C32 "1nF" CAPC1005X55N 52.5,38.1 r180 bottom
C33 "100nF" CAPC1005X55N 11.4,9.075 r90 top
D1 "BAT54CWT1G" SOT65P210X100-3AN 22.77,21.84 r180 bottom
D2 "ESD9B3.3ST5G" SODFL1006X43AN12 9.175,40.475 r180 bottom
D3 "ESD9B3.3ST5G" SODFL1006X43AN12 9.175,39.525 r180 bottom
D4 "597-3021-507F" LEDM3020X130N 3.356,2.402 r0 top
D5 "597-3301-507F" LEDM3020X130N 10.795,12.319 r0 top
FIDUCIAL1 "40mil FID" fiducial_40mil_round 4.5,5.9 r90 bottom
FIDUCIAL2 "40mil FID" fiducial_40mil_round 84.66,57.4 r90 top
FIDUCIAL3 "40mil FID" fiducial_40mil_round 4.5,5.9 r90 top
FIDUCIAL7 "40mil FID" fiducial_40mil_round 82.2,57.2 r90 bottom
FIDUCIAL8 "40mil FID" fiducial_40mil_round 4.9,55 r90 bottom
FIDUCIAL9 "40mil FID" fiducial_40mil_round 67.4,2.2 r90 top
FIL1 "25VDC/6A" FIL_ELKEA 10.422,27.69 r180 top
J1 "CC8X (55001984-02)" CC8X_CASTELLATED 37.973,30.988 r270 top locked
J2 "CSCD443CCS011B00G" conn_CSCD443CCS011B00G 12.319,19.939 r0 top
J3 "500873-0806" MOLEX_500873-0806 4.826,33.528 r270 bottom locked
J4 "1x2P" MOLEX_53047-0210 2.667,50.185 r90 top
J5 "1x4" MOLEX_53047-0410 2.68,40.908 r90 top
J6 "RJ45" XMultiple_XMG-9799-8821 76.503,21.558 r90 top locked
J7 "DF14A-20P-1.25H(25)" HIROSE_DF14A-20P-1.25H 27.453,4.244 r0 bottom locked
J8 "SFW15S-2STE1LF" FCI_SFW15S-2STE1LF 27.433,3.519 r180 top locked
J9 "KUSBX-AS2N" KYCON_KUSBX-AS2N 71.421,5.207 r90 top locked
J10 "KMMX-ABSMT5SG-30TR" KYCON_KMMX-ABSMT5 84.455,8.883 r270 bottom locked
J11 "61304021121" Wurth_61304021121 8.89,58.293 r0 top
J12 "SQT-110-01-F-S" SAMTEC_SQT-110-01-F-S 85.217,60.325 r180 top
J13 "SQT-110-01-F-S" SAMTEC_SQT-110-01-F-S 85.217,38.354 r180 top locked
J14 "1x2" FCI_68002-102HLF 8.6,43.6 r0 top
J15 "1x2" FCI_68002-102HLF 8.6,47.1 r0 top
J16 "1x2" FCI_68002-102HLF 8.6,50.6 r0 top
J17 "A2-20PA-2.54DSA(71)" HIROSE_A2-20PA-2.54DSA(71) 33.02,55.626 r0 top locked
J18 "GBC05SBSN-M89" SULLINS_GBC05SBSN-M89 50.8,7.112 r0 bottom locked
J19 "FTSH-105-01-F-DV" SAMTEC_FTSH-105-01-F-DV 73.279,45.466 r270 top
L1 "220" INDC2013X110N 50.2,24.7 r270 bottom
L2 "DLP11SN900" FIL_DLP11S 37.461,9.119 r270 bottom
L3 "DLP11SN900" FIL_DLP11S 33.752,9.187 r270 bottom
L4 "DLP11SN900" FIL_DLP11S 29.942,9.187 r270 bottom
L5 "DLP11SN900" FIL_DLP11S 26.259,9.187 r270 bottom
L6 "DLP11SN900" FIL_DLP11S 22.449,9.187 r270 bottom
L7 "220" INDC2013X110N 14.4,9.3 r0 bottom
L8 "220" INDC2013X110N 66.8,9.8 r180 top
L9 "220" INDC2013X110N 66.8,7.7 r180 top
L10 "744231121" FIL_DLW21H 60.825,9.35 r0 bottom
L11 "744231121" FIL_DLW21H 60.825,11.8 r0 bottom
L12 "220" INDC2013X110N 66.8,11.9 r0 top
L13 "220" INDC2013X110N 66.8,14 r0 top
L14 "220" INDC2013X110N 82,2.7 r90 bottom
L15 "220" INDC2013X110N 81.742,47.392 r90 bottom
L16 "220" INDC2013X110N 84.056,47.392 r90 bottom
PCB1 "PCB" PCBNUMBER 71.728,80.505 r90 top
Q1 "2N7002T" SOTFL50P160X80_GSD-3N 56.9,35.3 r180 bottom
R1 "0.0" RESC2013X70N 6.1,43.4 r90 top
R2 "0.0" RESC2013X70N 6.1,47.2 r270 top
R3 "0" RESC1005X40N 32.2,11.5 r180 bottom
R4 "100K" RESC1005X40N 58.42,3.556 r270 top
R5 "100K" RESC1005X40N 48.387,3.556 r270 top
R6 "12K" RESC1609X55N 24.3,18.3 r90 bottom
R7 "20K" RESC1609X55N 22.8,15.3 r0 bottom
R8 "0.0" RESC2013X70N 6.1,51 r90 top
R9 "0" RESC1005X40N 17.825,20.1 r0 bottom
R10 "4.7K" RESC1005X40N 6,35.95 r0 top
R11 "100K" RESC1005X40N 5.969,37.225 r180 top
R12 "100K" RESC1005X40N 5.975,28.3 r180 top
R13 "4.7K" RESC1005X40N 5.969,29.337 r0 top
R14 "22.1K" RESC1005X40N 18.669,30.861 r0 bottom
R15 "10.0K" RESC1005X40N 18.669,32.131 r0 bottom
R16 "10.0K" RESC1005X40N 18.669,33.401 r0 bottom
R17 "10.0K" RESC1005X40N 18.669,27.051 r0 bottom
R18 "10.0K" RESC1005X40N 18.669,28.321 r0 bottom
R19 "100" RESC1005X40N 18.669,29.591 r180 bottom
R20 "0.0" RESC2013X70N 18.9,23.7 r180 bottom
R22 "1.0K" RESC1005X40N 56.7,29.2 r270 bottom
R23 "1.0K" RESC1005X40N 60.4,27.1 r0 bottom
R24 "4.7K" RESC1005X40N 60.4,24.6 r0 bottom
R25 "4.7K" RESC1005X40N 60.4,25.9 r0 bottom
R26 "4.7K" RESC1005X40N 59.893,32.258 r0 bottom
R27 "4.7K" RESC1005X40N 59.893,28.448 r0 bottom
R28 "4.7K" RESC1005X40N 59.893,29.718 r0 bottom
R29 "4.7K" RESC1005X40N 59.893,31.018 r0 bottom
R30 "4.7K" RESC1005X40N 60.853,32.258 r0 bottom
R31 "4.7K" RESC1005X40N 60.853,28.448 r0 bottom
R32 "4.7K" RESC1005X40N 60.853,29.718 r0 bottom
R33 "4.7K" RESC1005X40N 60.853,31.018 r0 bottom
R34 "49.9" RESC1005X40N 64,20 r180 top
R35 "49.9" RESC1005X40N 64,23.6 r180 top
R36 "49.9" RESC1005X40N 64,28.35 r180 top
R37 "49.9" RESC1005X40N 64,24.8 r180 top
R38 "12.1k" RESC1005X40N 53.5,21.3 r0 bottom
R39 "0" RESC1005X40N 64,30.9 r90 top
R40 "150" RESC1005X40N 64,36.8 r180 top
R41 "150" RESC1005X40N 64,35.5 r0 top
R42 "0" RESC3225X60N 65.1,16.8 r0 top
R43 "10.0K" RESC1005X40N 16.8,9.3 r270 bottom
R44 "0" RESC1005X40N 63.825,8.75 r0 bottom
R45 "0" RESC1005X40N 63.825,9.95 r0 bottom
R46 "0" RESC1005X40N 63.825,11.2 r0 bottom
R47 "0" RESC1005X40N 63.825,12.4 r0 bottom
R48 "0" RESC1005X40N 79.6,9.8 r180 bottom
R49 "0" RESC1005X40N 79.6,8.6 r180 bottom
R50 "0" RESC1005X40N 78.2,57.3 r0 top
R51 "0" RESC1005X40N 75.5,57.3 r180 top
R52 "0" RESC1005X40N 73.3,57.3 r0 top
R53 "0" RESC1005X40N 71.1,57.3 r180 top
R54 "10.0K" RESC1005X40N 68.599,57.331 r0 top
R55 "0" RESC1005X40N 79.2,42.2 r90 top
R56 "0" RESC1005X40N 77.8,42.2 r90 top
R57 "10.0K" RESC1005X40N 80.6,42.2 r270 top
R58 "0" RESC1005X40N 67.2,42.2 r90 top
R59 "120" RESC1005X40N 2.003,3.545 r90 bottom
R60 "10.0K" RESC1005X40N 8.8,6.2 r90 bottom
R61 "120" RESC1005X40N 10.189,7.155 r270 bottom
R62 "0" RESC1005X40N 82.2,57 r90 top
R63 "0" RESC1005X40N 80.8,57 r90 top
R64 "0" RESC1005X40N 23.375,46.095 r270 bottom
R65 "0" RESC1005X40N 22.175,46.095 r270 bottom
R66 "0" RESC1005X40N 23.375,47.055 r90 bottom
R67 "0" RESC1005X40N 22.175,47.055 r90 bottom
R68 "120" RESC1005X40N 10.922,12.319 r180 bottom
R69 "0" RESC1005X40N 9.2,41.5 r0 bottom
R70 "10.0K" RESC1005X40N 18.669,25.908 r0 bottom
R71 "0" RESC1609X55N 52.5,32.7 r180 bottom
R72 "10.0K" RESC1005X40N 55,35.4 r270 bottom
R73 "100K" RESC1005X40N 56.9,33.3 r180 bottom
R74 "2.2K" RESC1005X40N 29.807,7.807 r90 top
R75 "2.2K" RESC1005X40N 31.8,7.8 r90 top
R76 "0" RESC1005X40N 79.6,7.45 r180 bottom
R77 "0.0" RESC2013X70N 4.825,54.825 r180 top
S3 "TDA02H0SB1" SW_TDA02 2.413,32.131 r270 top
SW1 "KSC221JLFS" SW_KSC221J 54.379,3.572 r90 top
SW2 "KSC221JLFS" SW_KSC221J 44.346,3.572 r90 top
SW3 "KSC221JLFS" SW_KSC221J 11.019,3.683 r270 top
SWD "TC2050-IDC-NL" TC_TC2050-IDC-NL 73.279,53.594 r0 bottom
TP3 "TESTPOINT" TP0762 81.5,13.5 r270 bottom
U1 "AP2202" SOT95P280X145-5N 20.9,18.3 r180 bottom
U2 "SN74AVC2T245" QFN40P260X180X55-16N 19.496,46.205 r180 bottom
U3 "LAN8720Ai" QFN50P400X400X100-25T260X260N 55.4,24.9 r0 bottom
U4 "SI2323DS-T1-E3" SOT95P240X110_GSD-3N 52.4,35.4 r270 bottom
U9 "FXLP34P5X" SOT65P210X110-5N 14.625,9.25 r270 top

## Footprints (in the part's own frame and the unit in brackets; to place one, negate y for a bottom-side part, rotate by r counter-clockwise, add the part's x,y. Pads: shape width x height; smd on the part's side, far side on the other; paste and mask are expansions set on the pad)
CAPC1005X55L [mm]
  rect 0.52x0.52 smd mask+0.05: 1(-0.4,0) 2(0.4,0)
  body extent -0.5,-0.25 0.5,0.25, height 0.55
CAPC1005X55N [mm]
  rect 0.6x0.62 smd mask+0.05: 1(-0.46,0) 2(0.46,0)
  body extent -0.5,-0.25 0.5,0.25, height 0.55
CAPC1608X90N [mm] "0603"
  rrect22% 0.89x0.93 smd: 1(-0.77,0) 2(0.77,0)
  body extent -0.8,-0.4 0.8,0.4, height 0.9
CAPC2013X135N [mm] "0805, 1.35mm max height"
  rect 1.05x1.4 smd: 1(-0.9,0) 2(0.9,0)
  body extent -1.1,-0.72 1.1,0.72, height 1.35
CAPC2013X145N [mm] "0805, 1.45mm max height"
  rect 1.15x1.45 smd: 1(-0.9,0) 2(0.9,0)
  silkscreen extent -1.47,-0.98 1.47,0.98, body extent -1.05,-0.67 1.05,0.68, height 1.45
CAPC3216X190N [mm]
  rect 1.15x1.8 smd: 1(-1.5,0) 2(1.5,0)
  body extent -1.6,-0.8 1.6,0.8, height 1.9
